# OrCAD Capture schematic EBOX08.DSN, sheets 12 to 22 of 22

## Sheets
12 13 HDMI: size A4
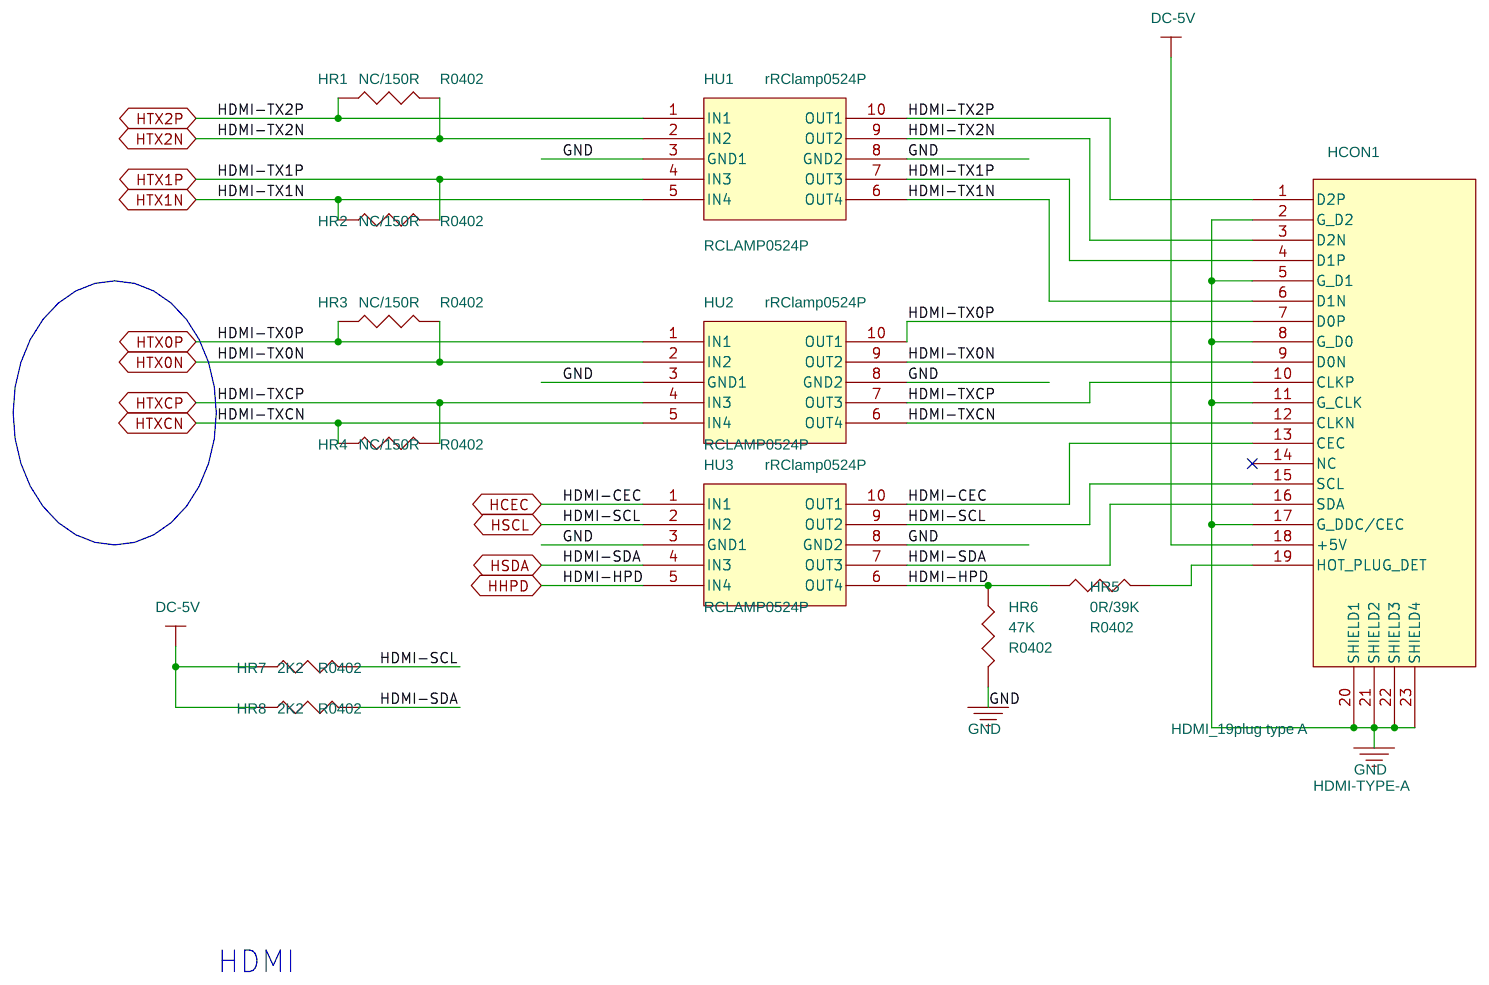
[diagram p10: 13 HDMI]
13 14 UART0-EMAC: size A2
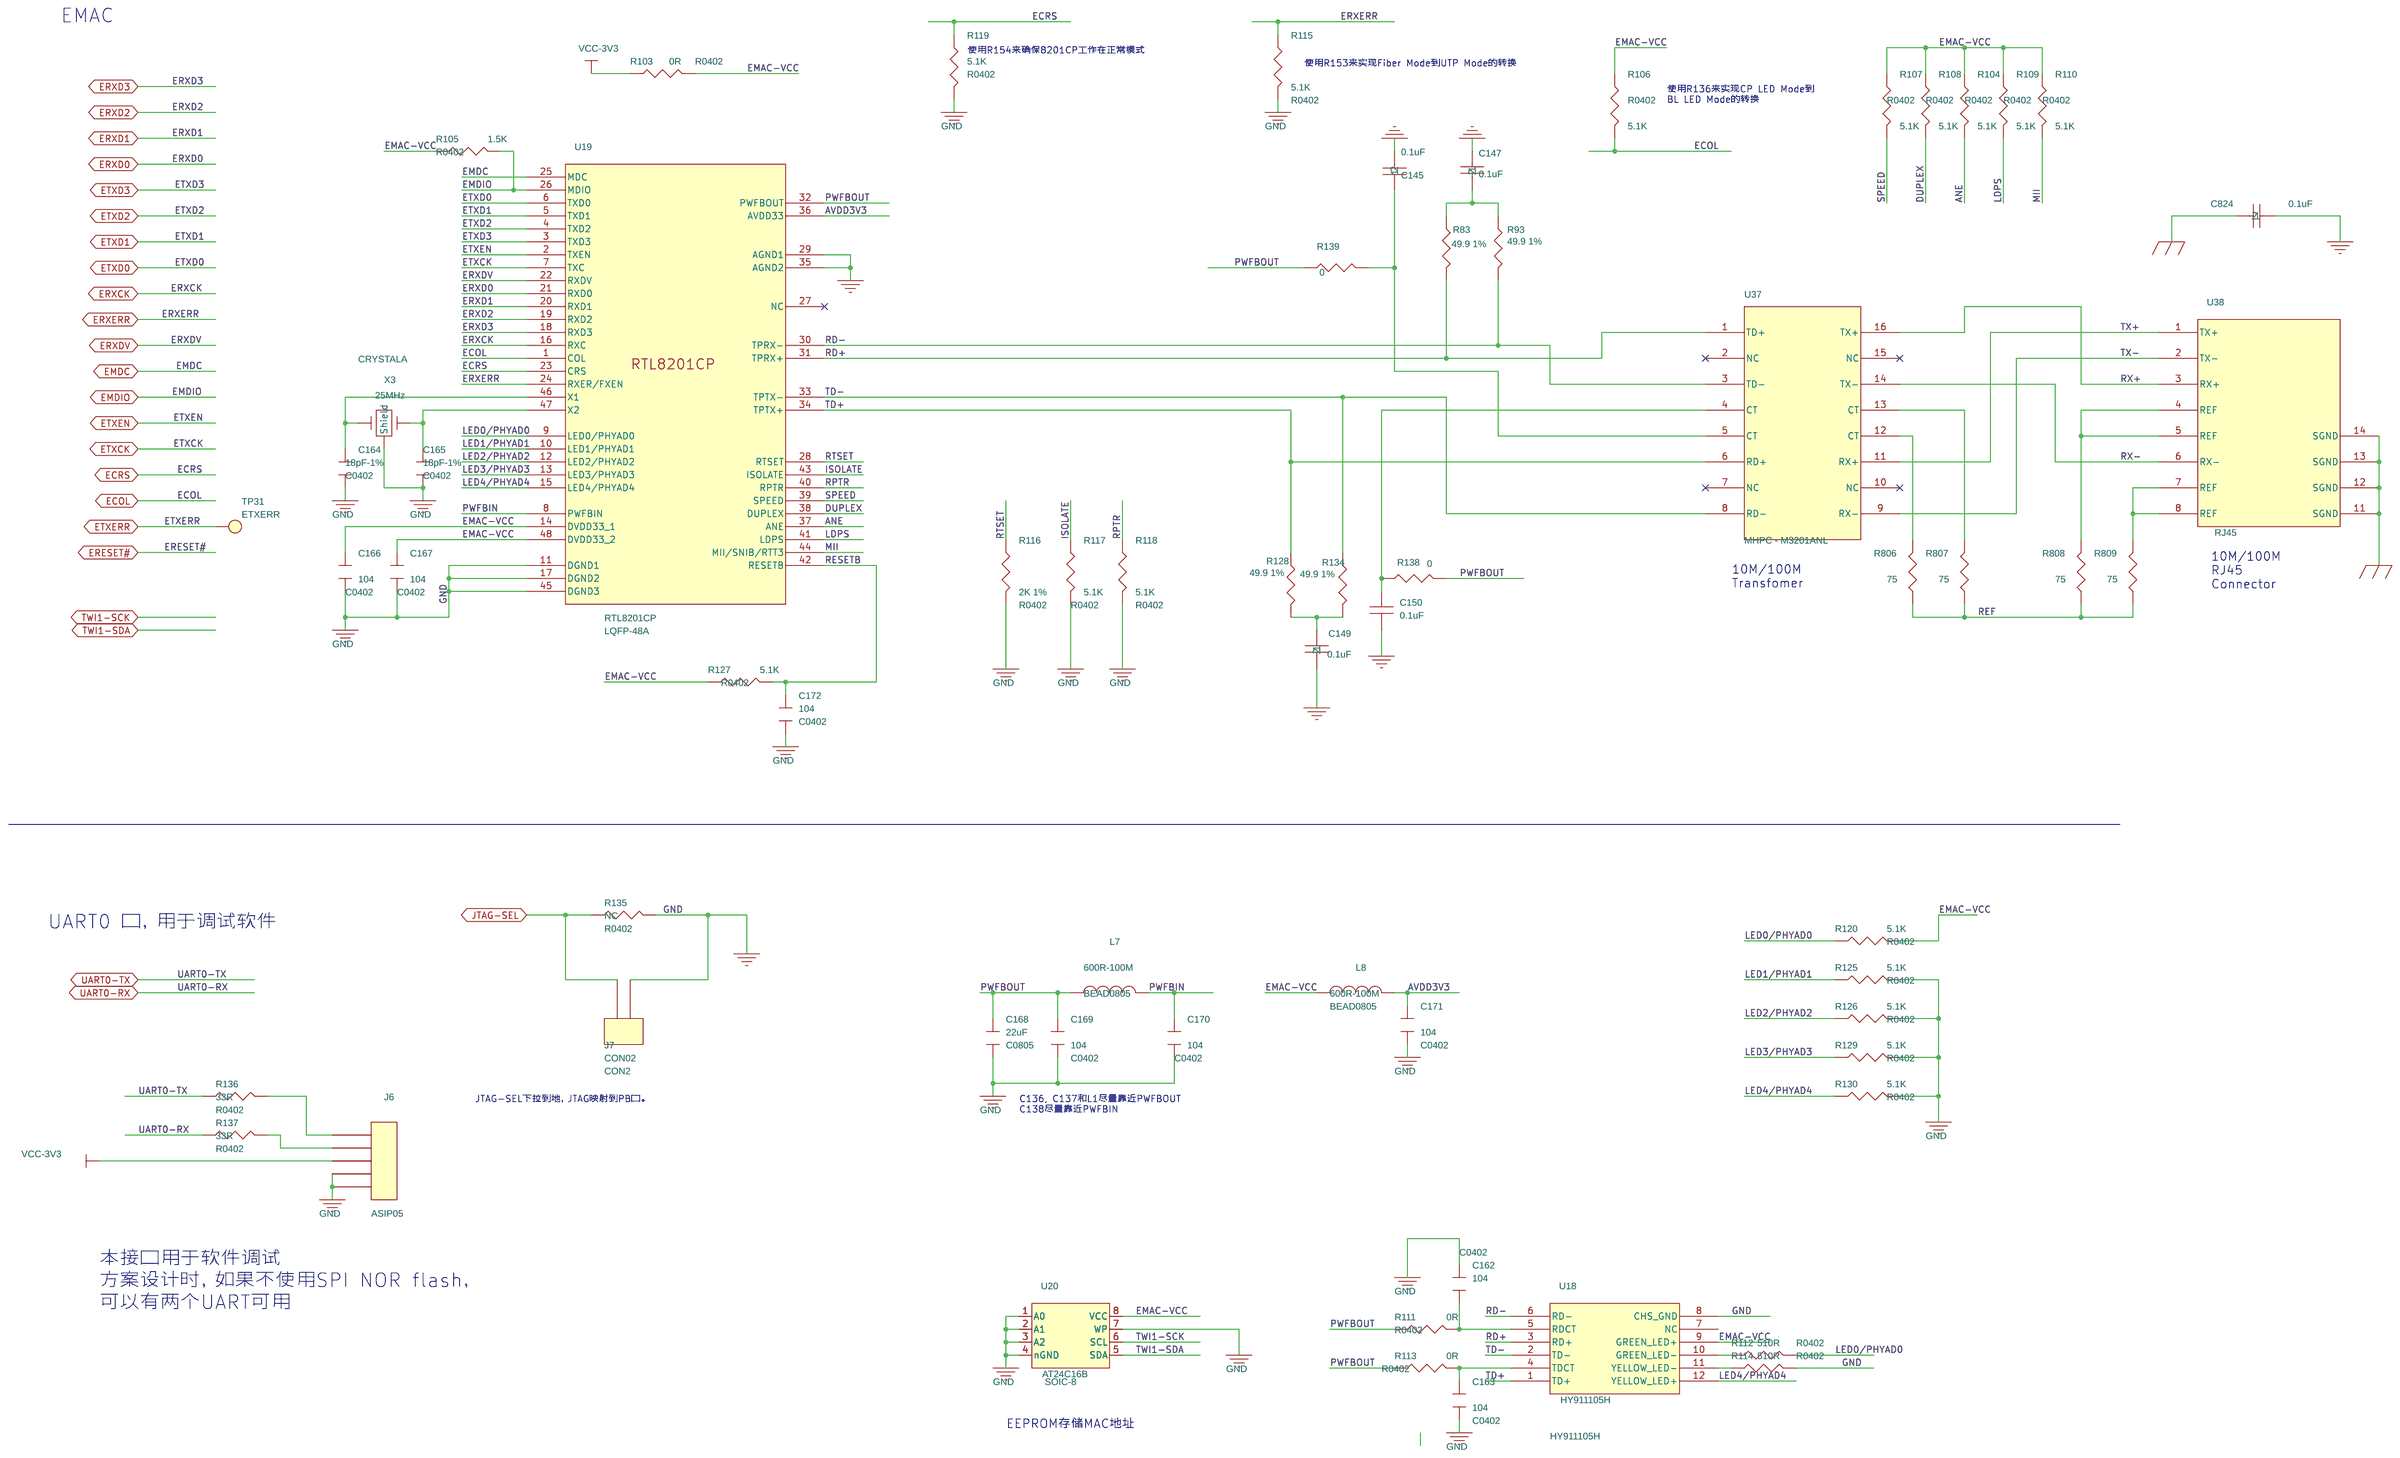
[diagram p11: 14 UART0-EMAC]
14 15 KEY-IR-LED: size A3
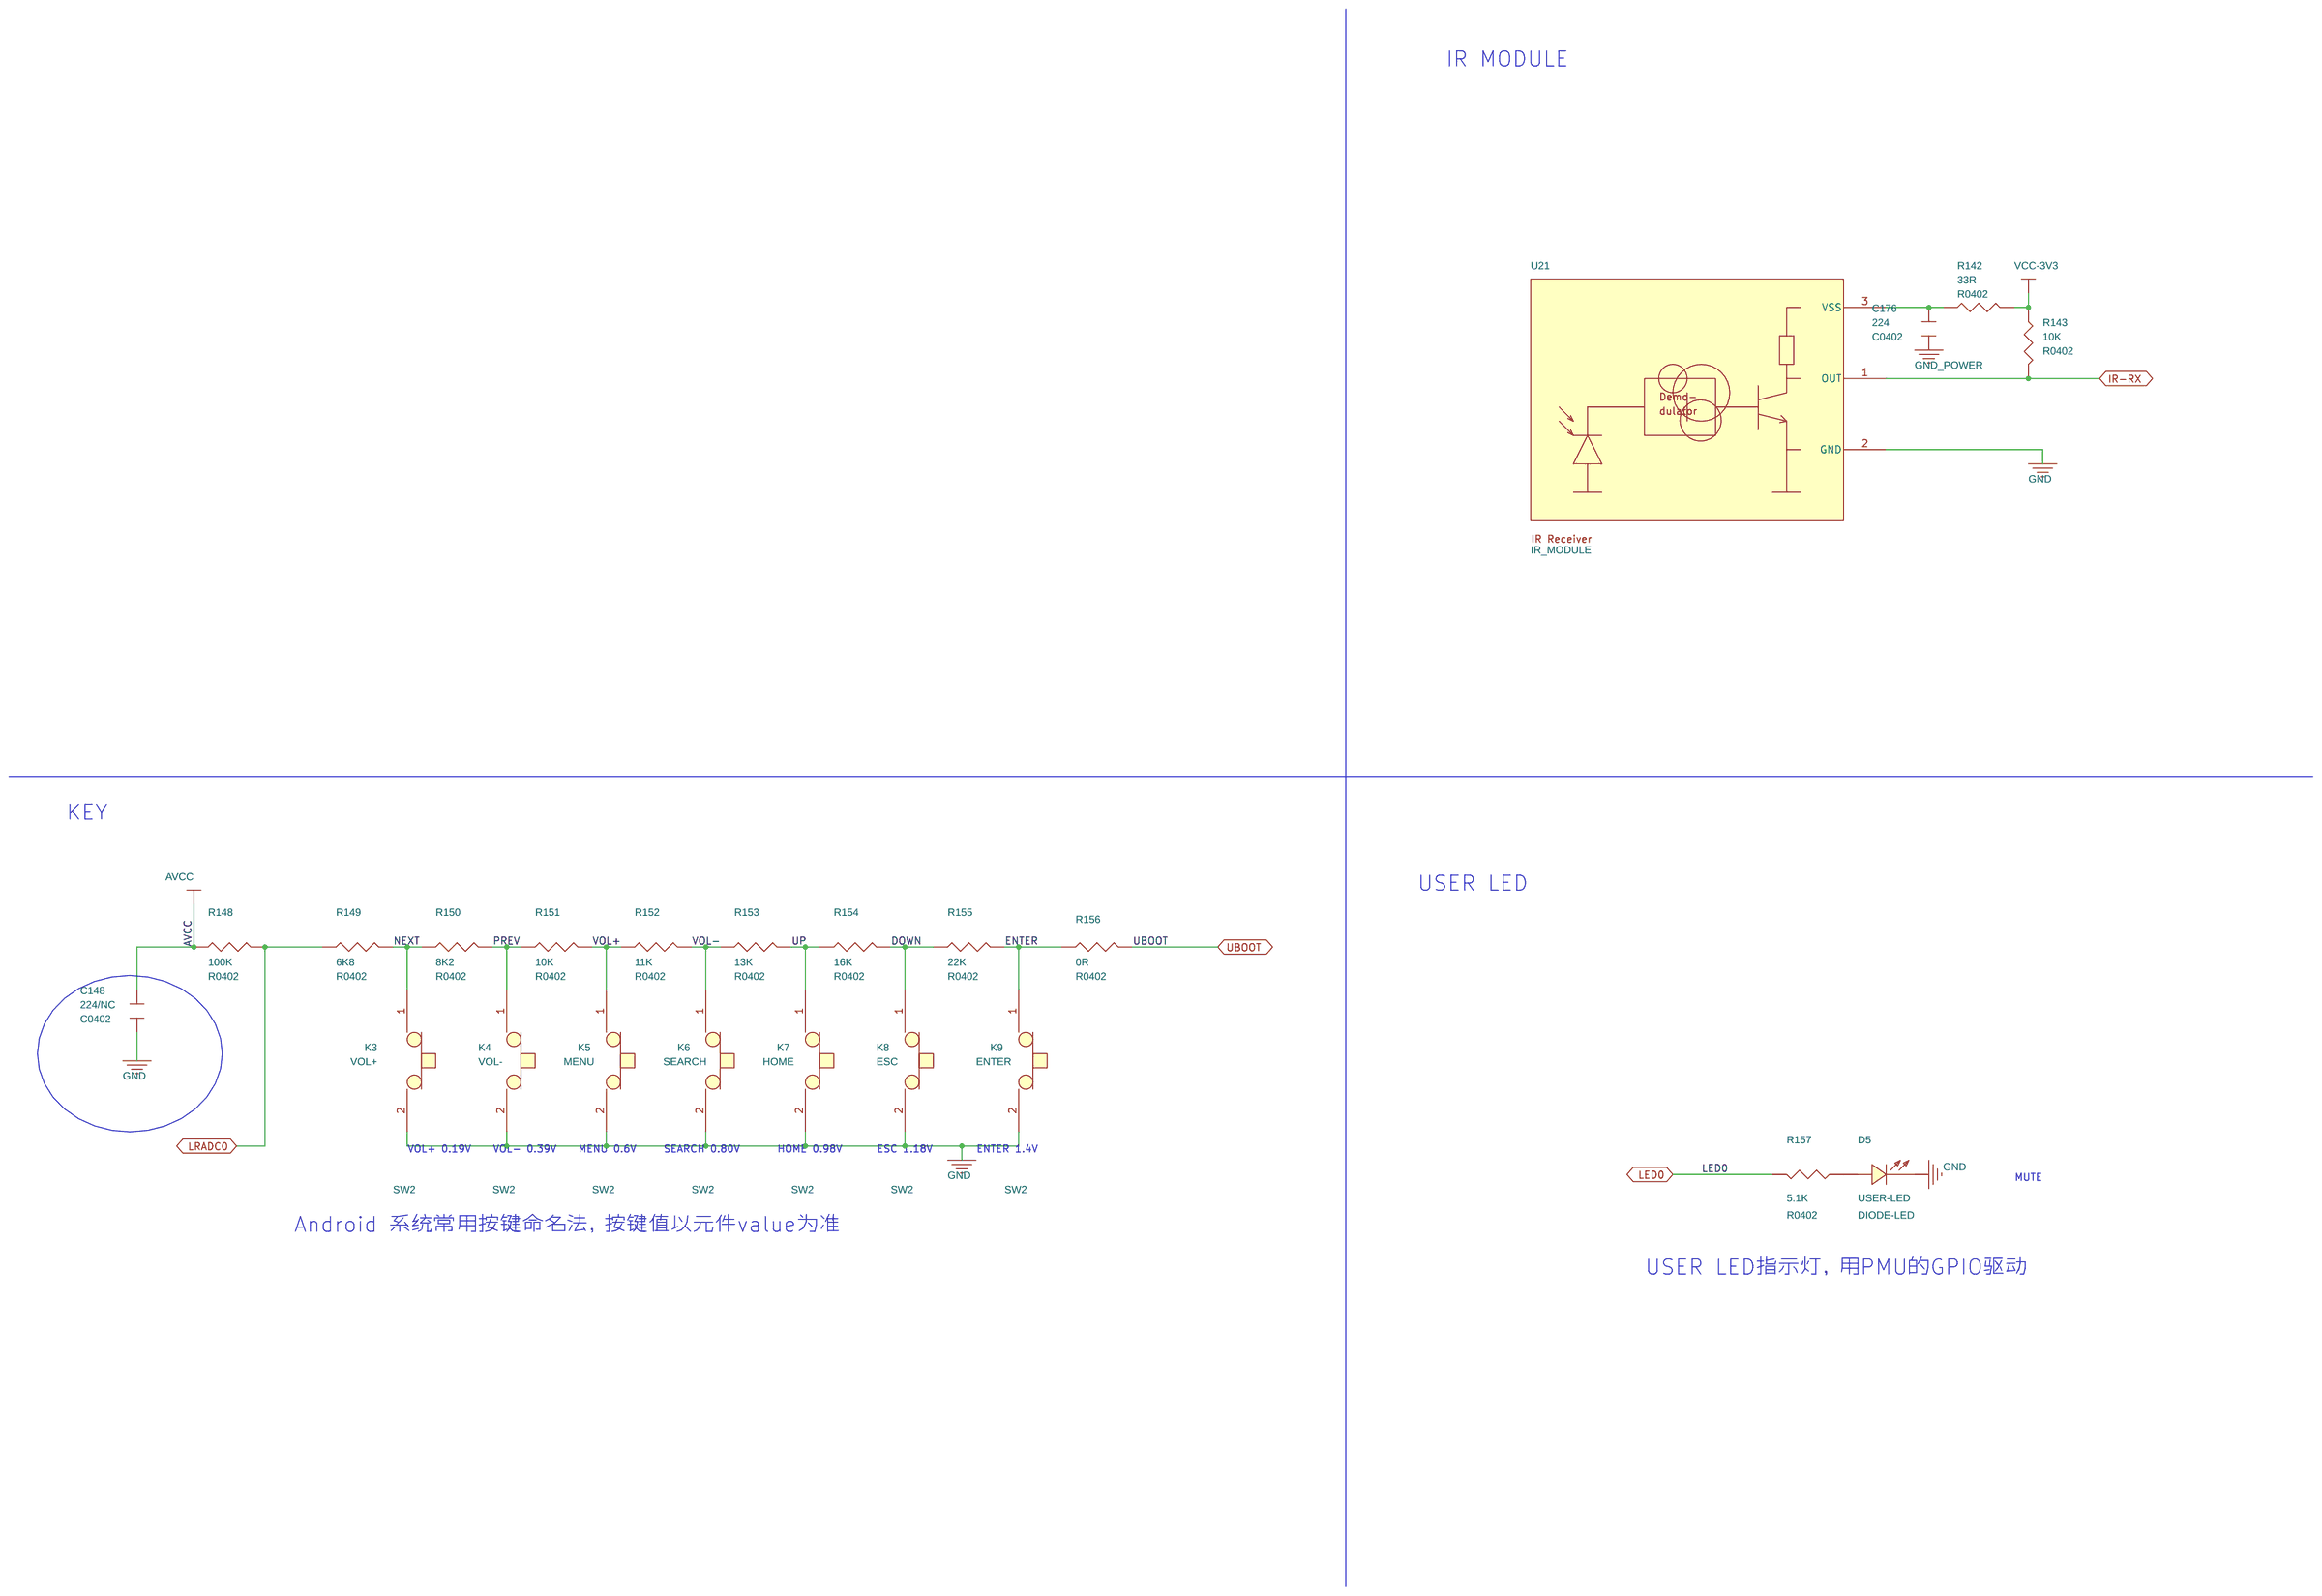
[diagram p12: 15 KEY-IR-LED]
15 16 NC
16 17 SPDIF-OUT: size A4
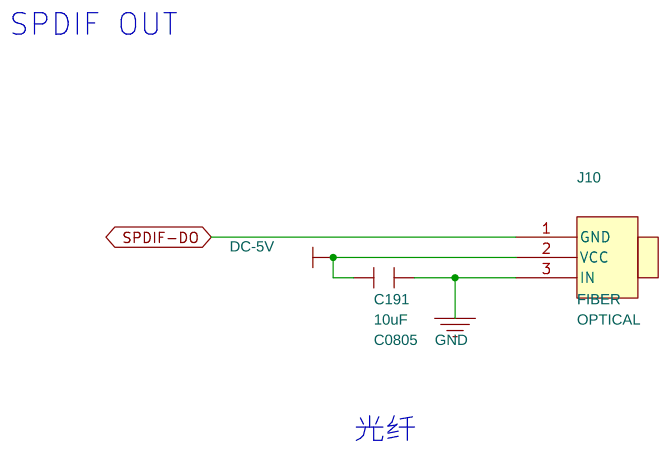
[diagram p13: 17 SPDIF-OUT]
17 18 AUDIO-OUT: size A3
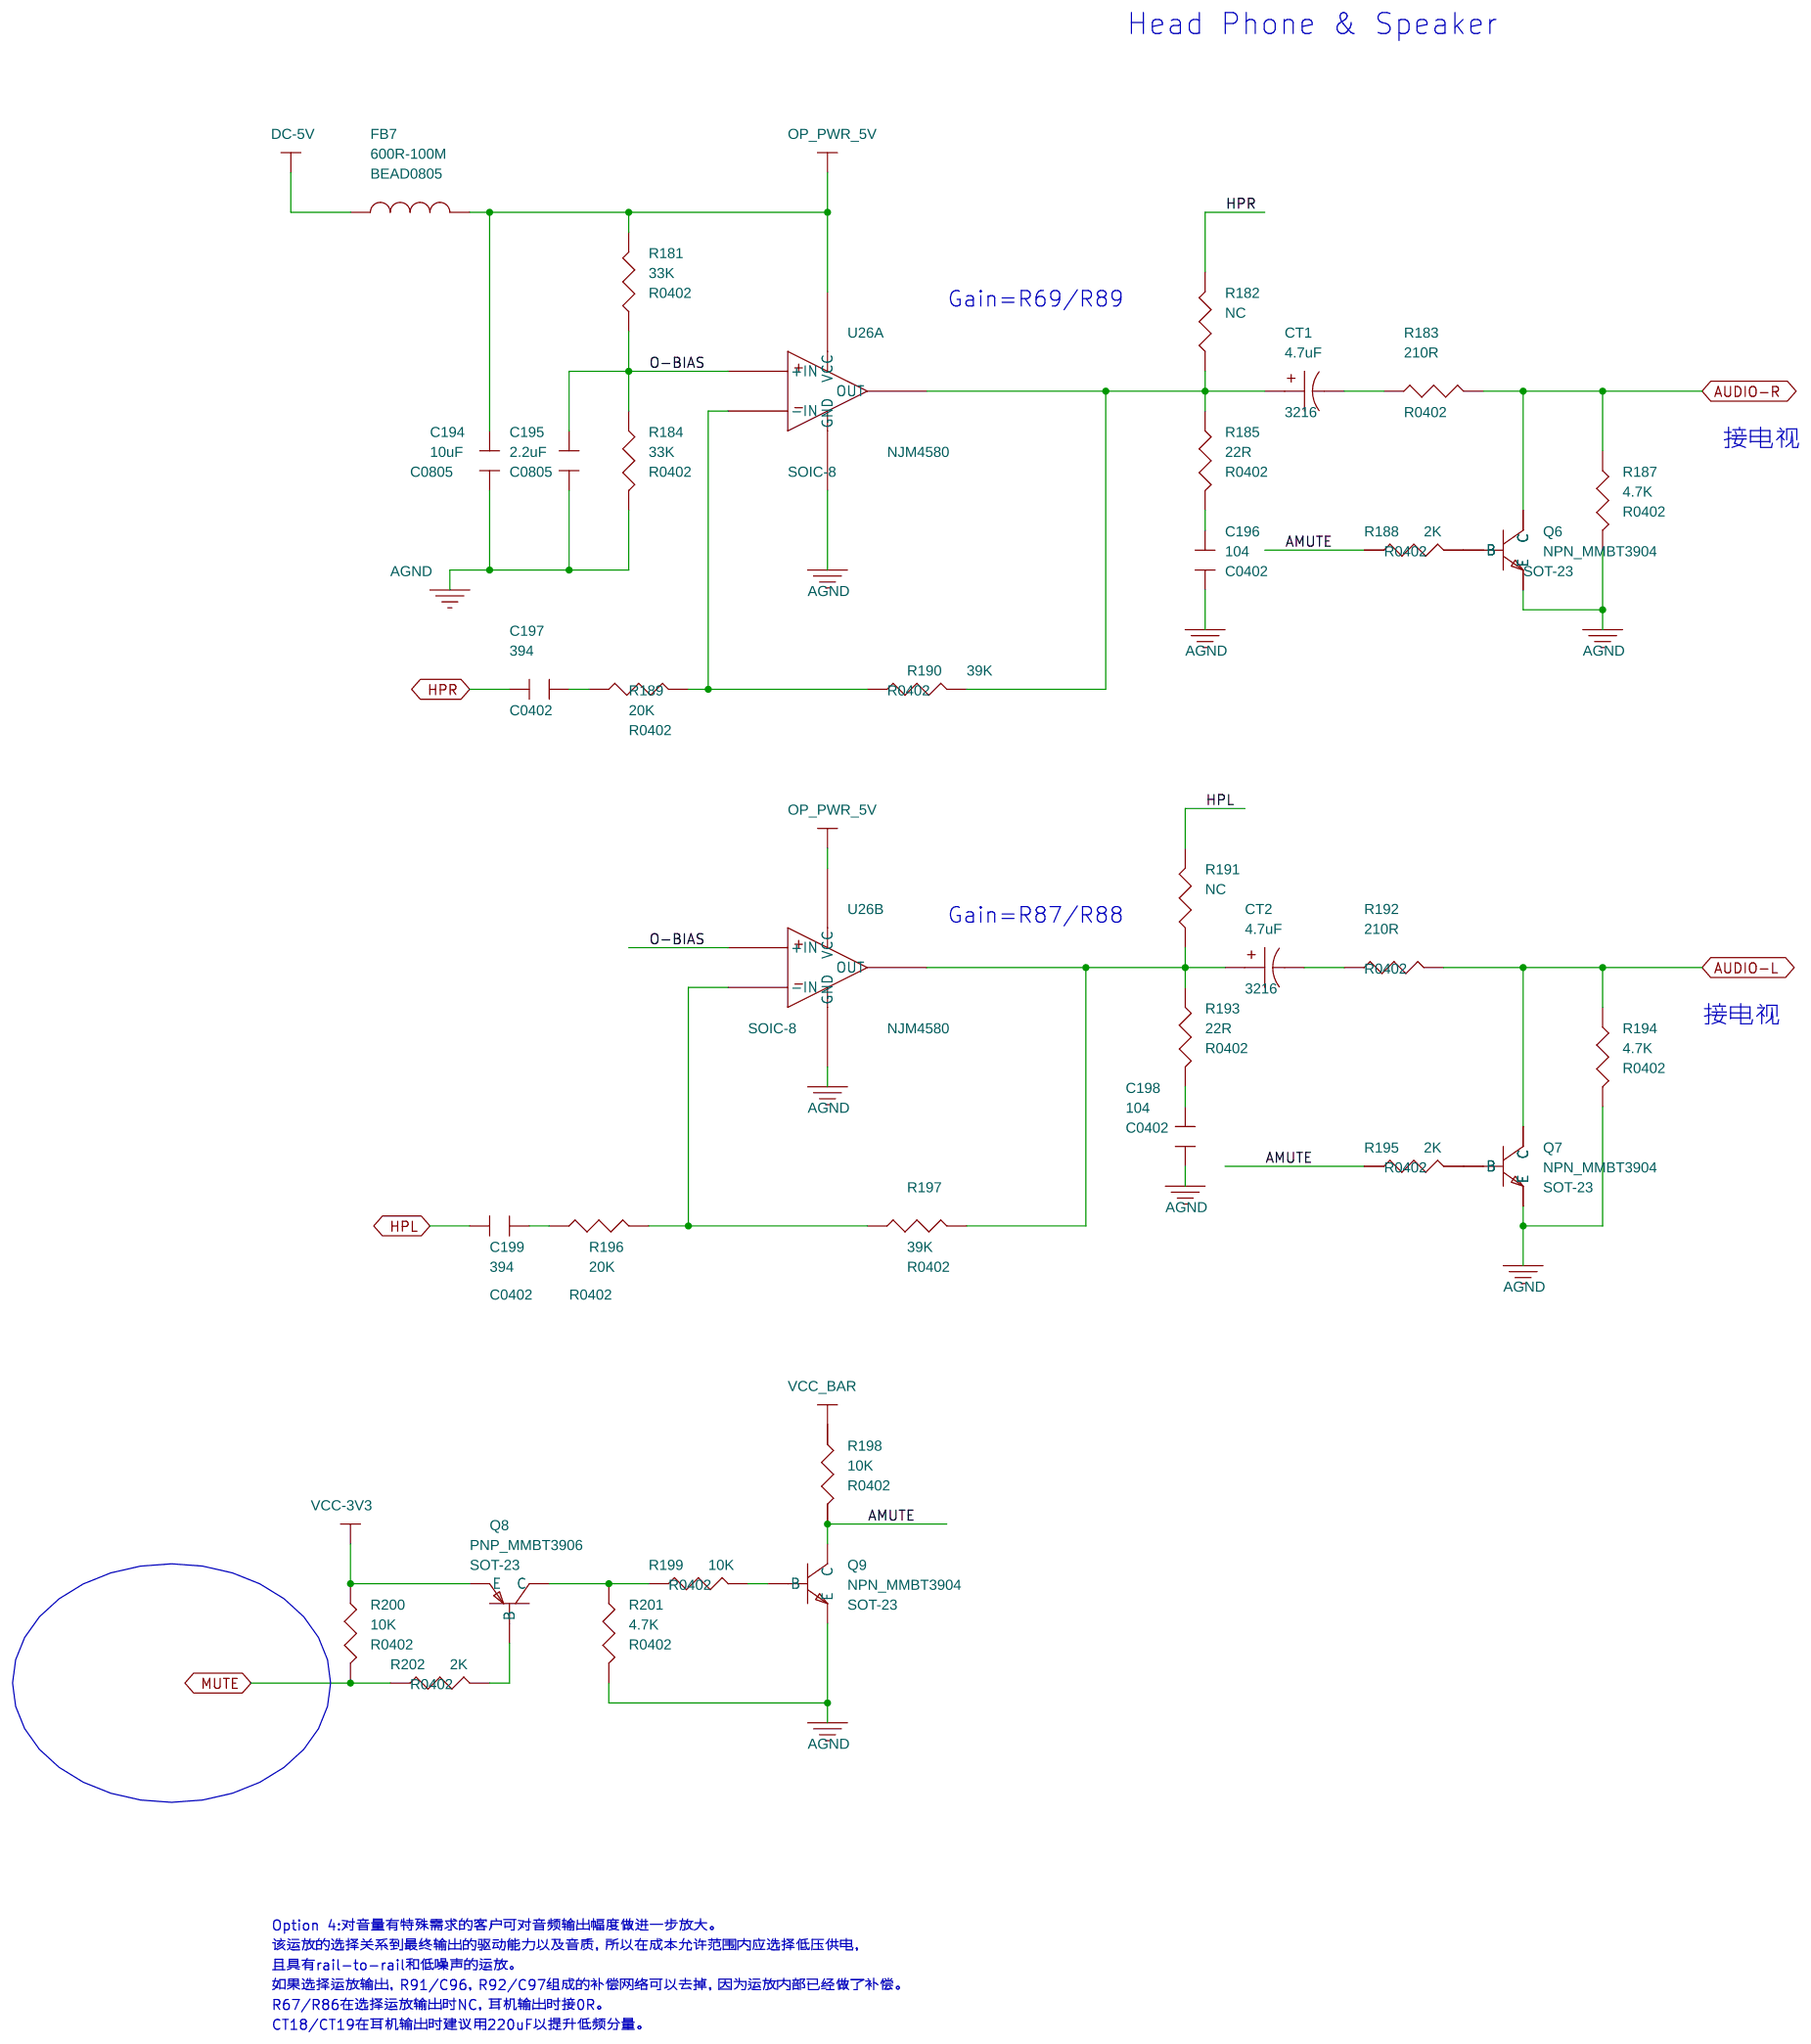
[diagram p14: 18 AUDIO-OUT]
18 19 CVBS-OUT: size A4
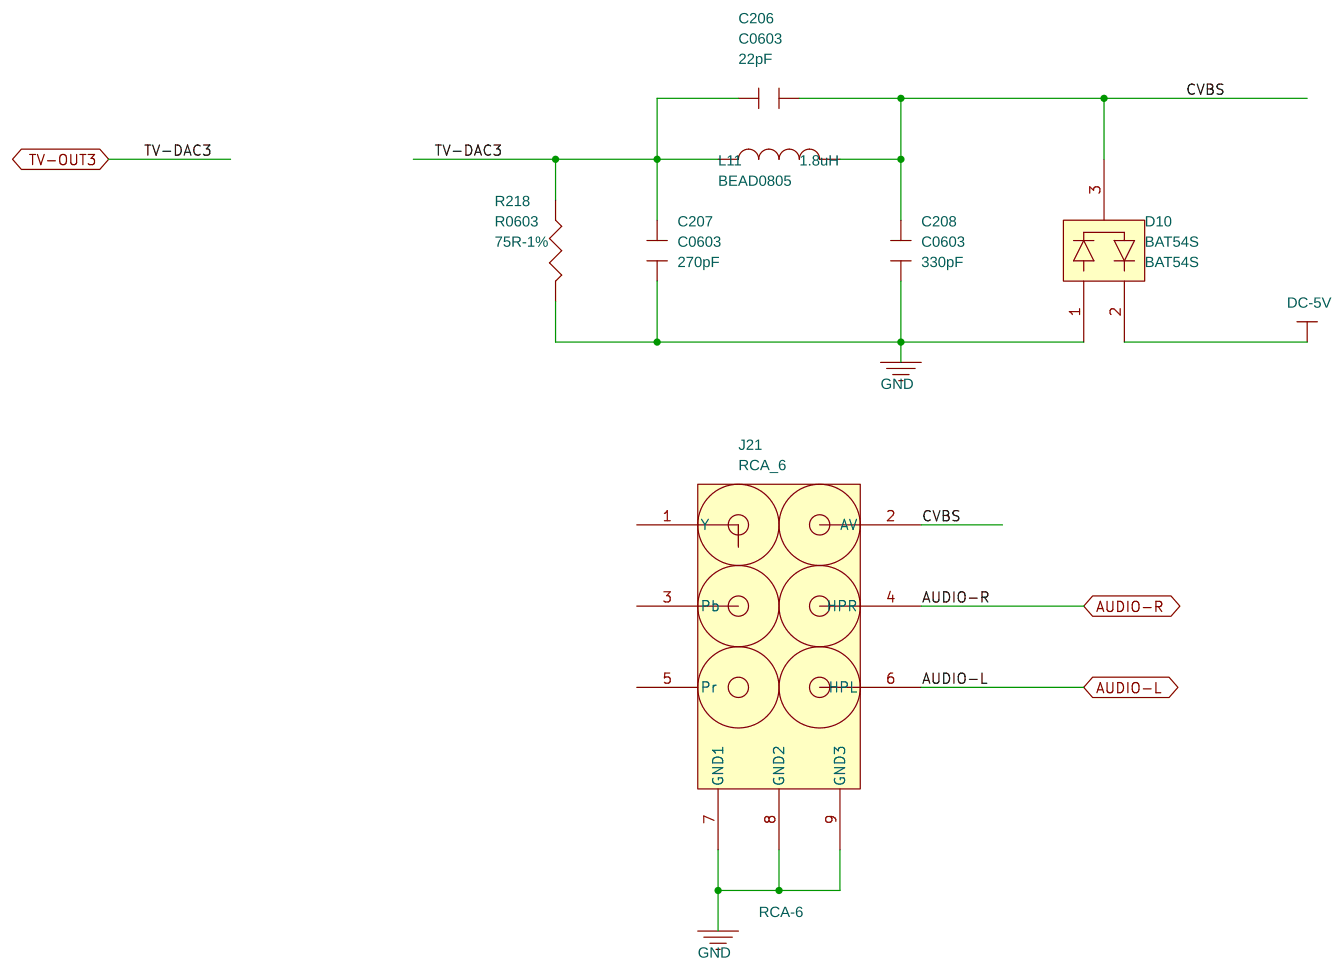
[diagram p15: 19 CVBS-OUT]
19 20 NC
20 21 NC
21 08 POWER/PMU: size A3
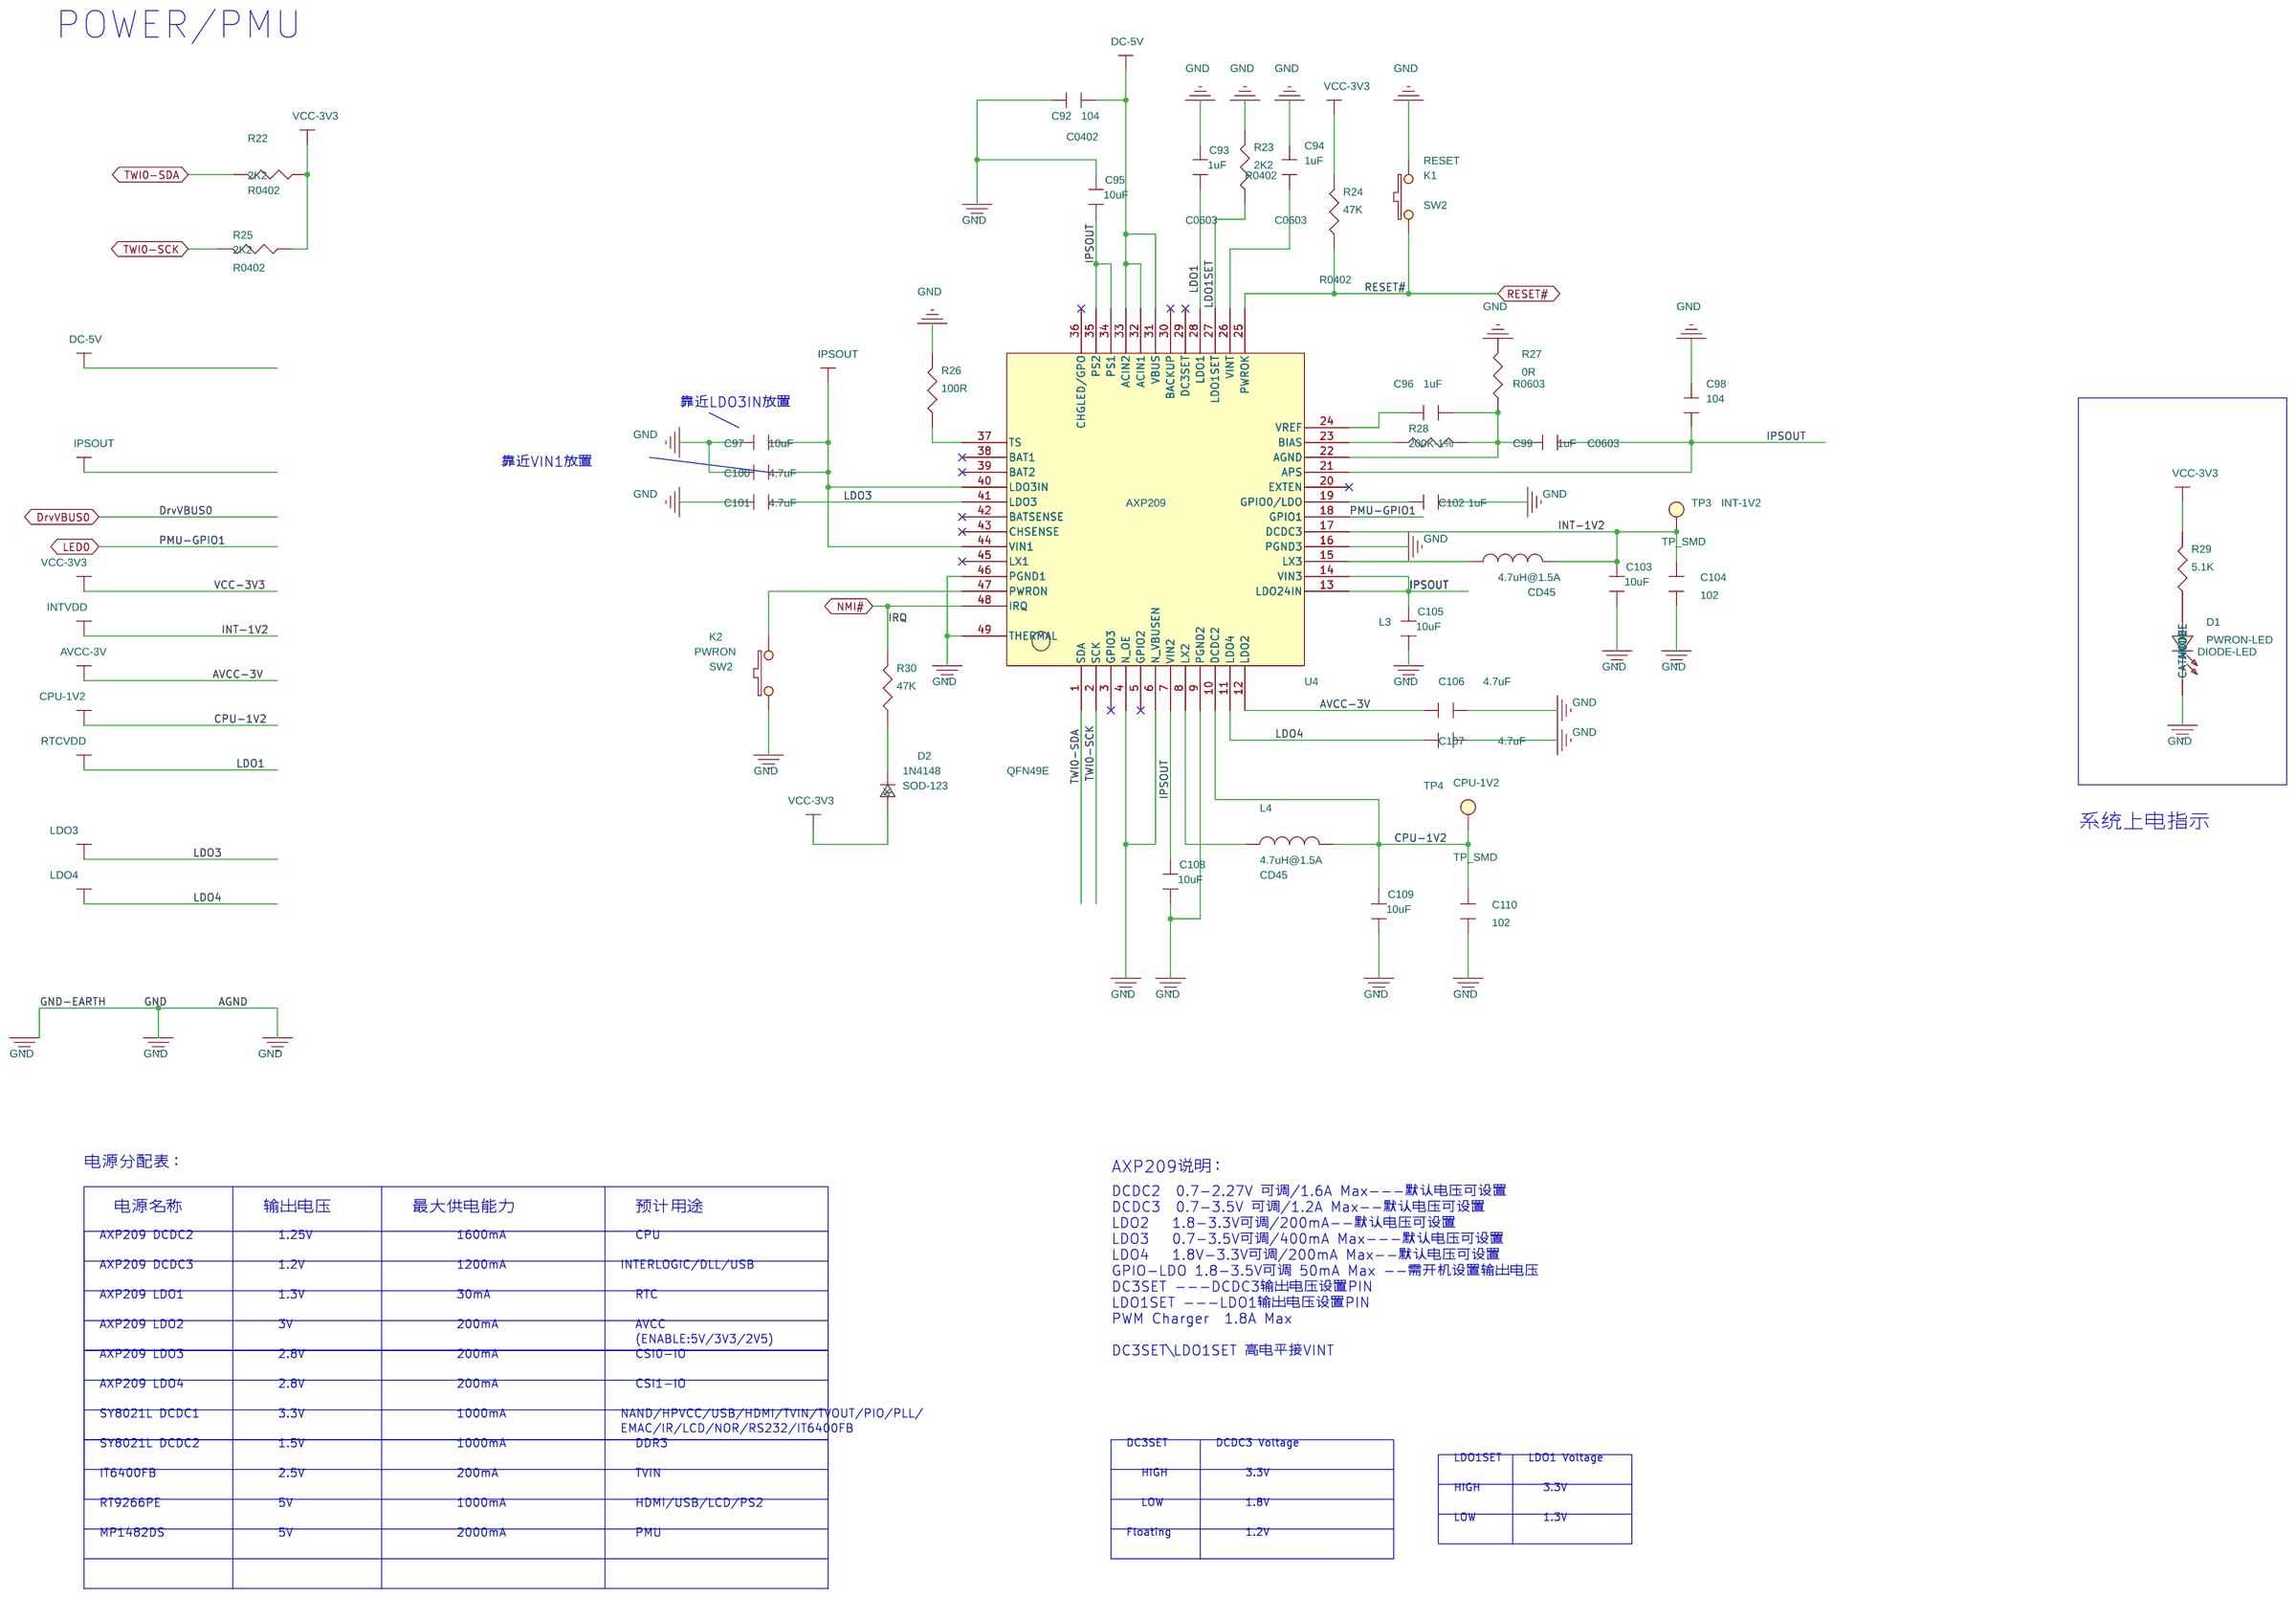
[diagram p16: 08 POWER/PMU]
22 07 POWER/DCDC: size A3
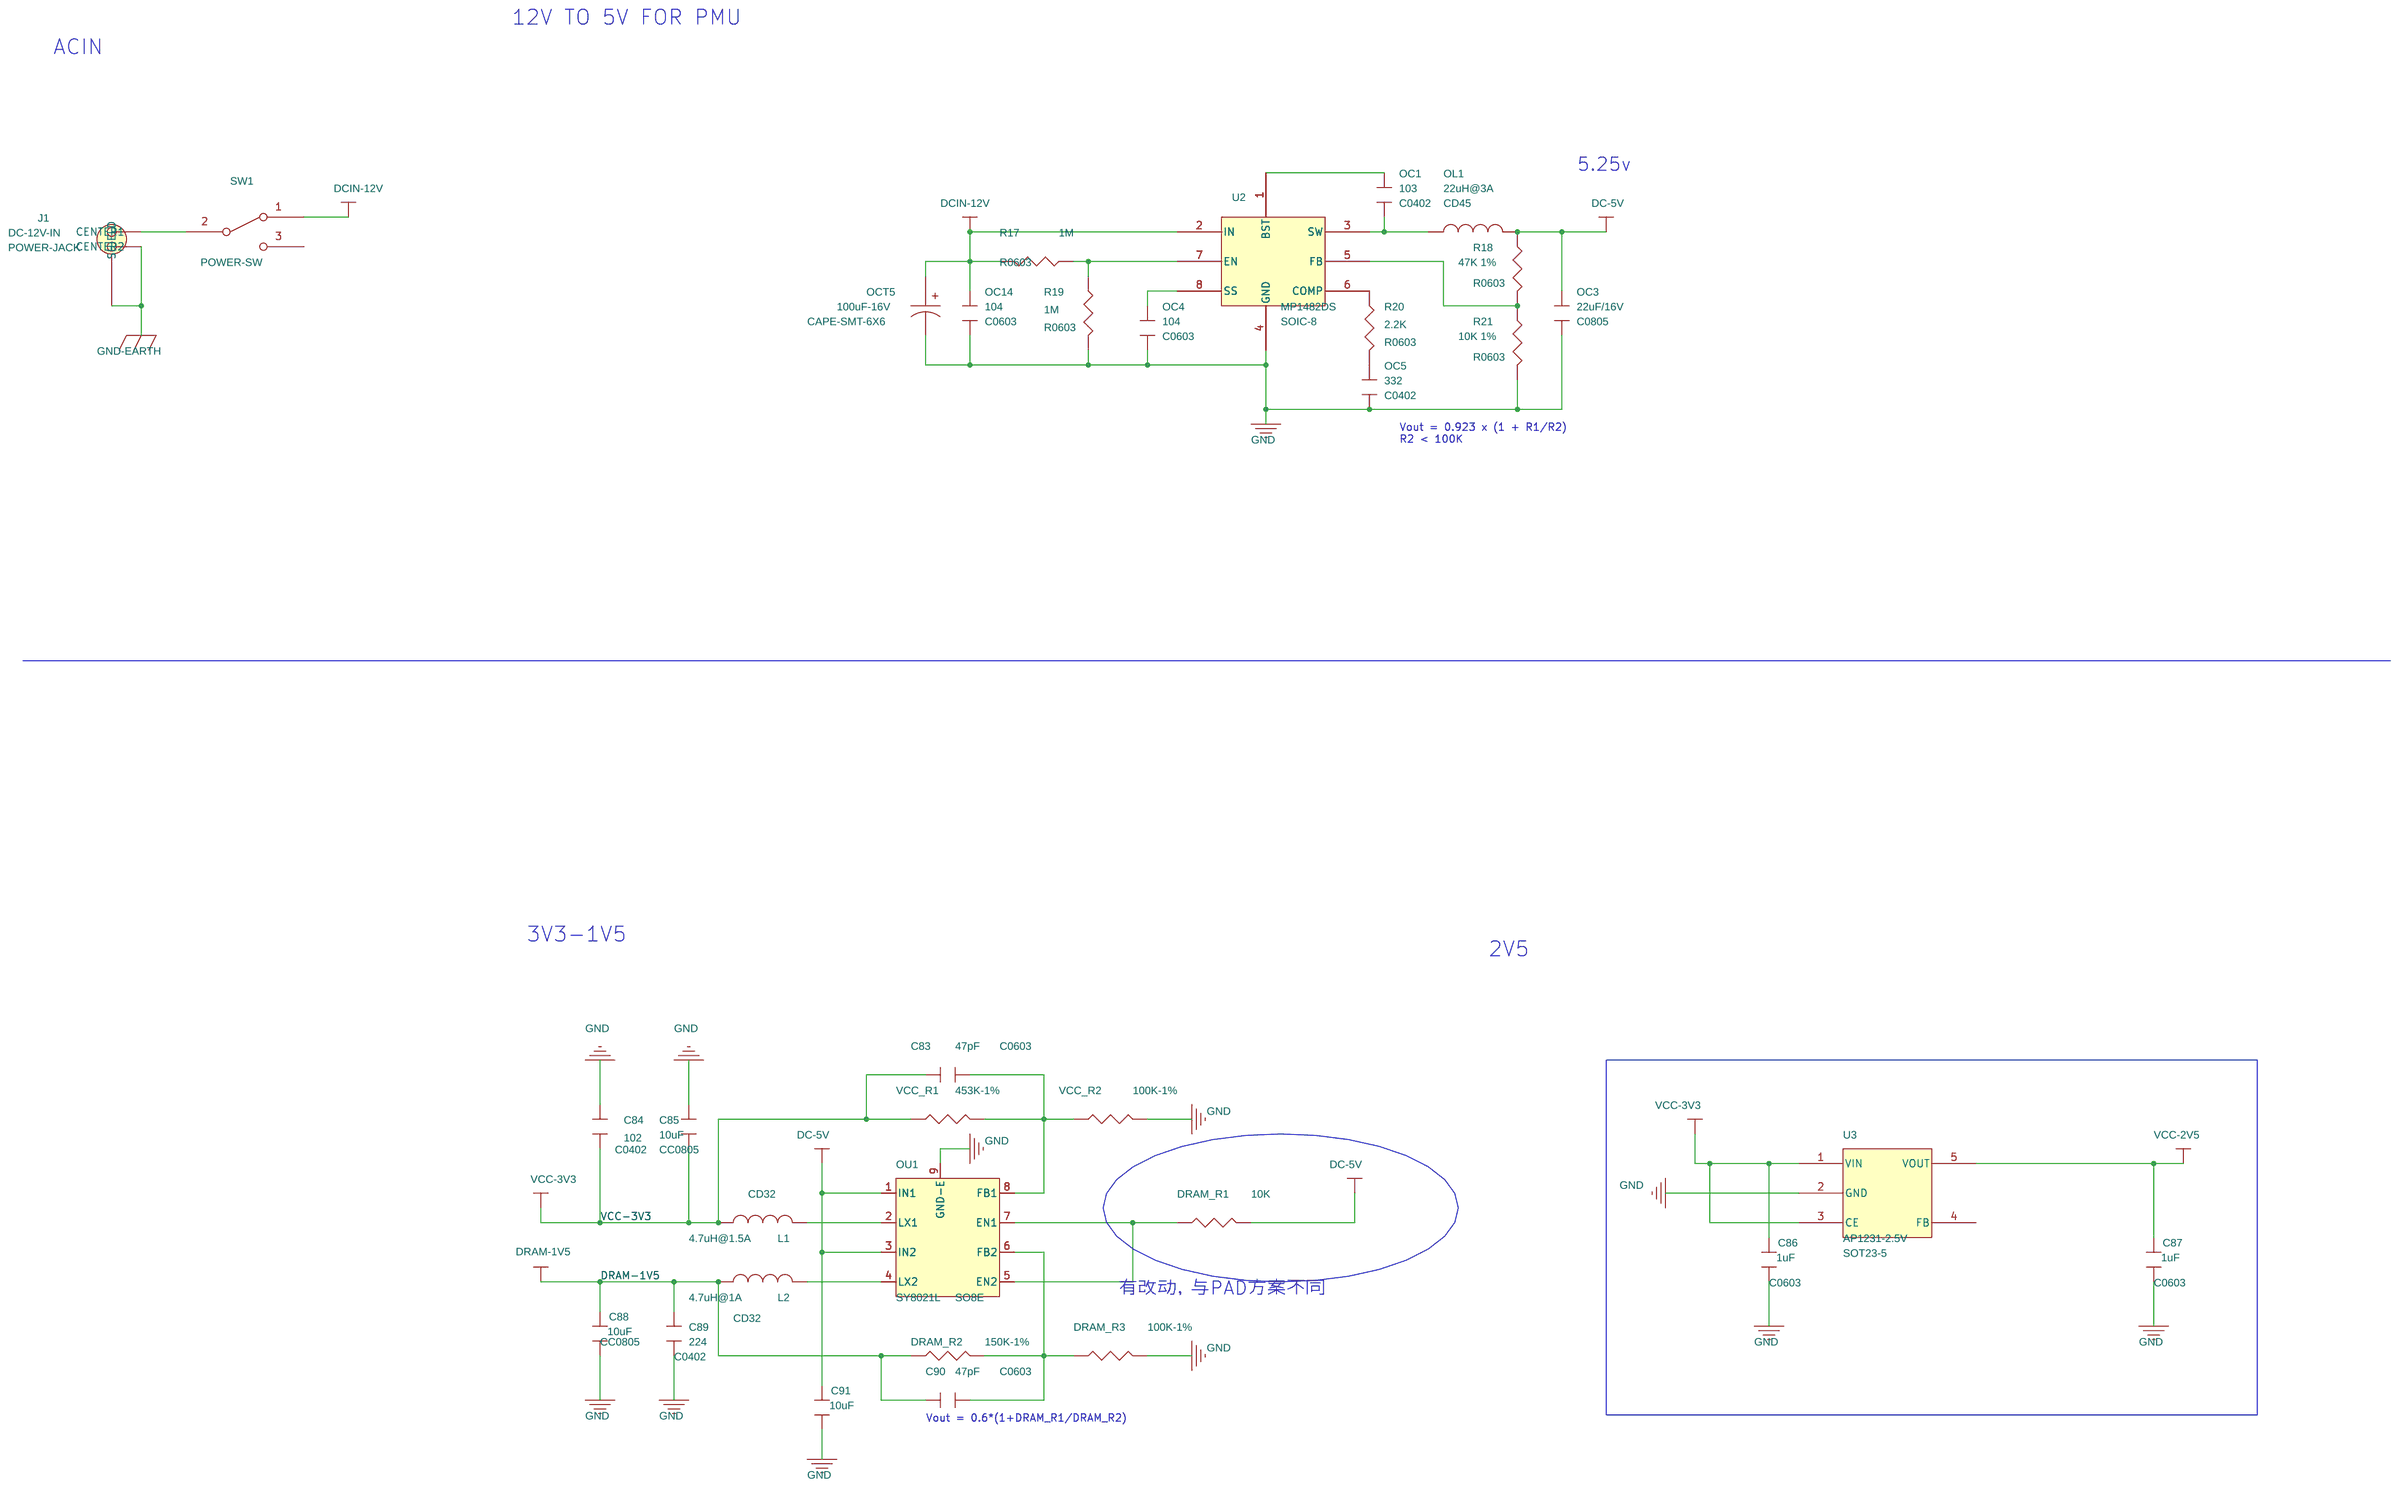
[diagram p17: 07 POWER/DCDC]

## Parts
sheet 07 POWER/DCDC
C83  47pF  [C0603]
C84  102  [C0402]
C85  10uF  [CC0805]
C86  1uF  [C0603]
C87  1uF  [C0603]
C88  10uF  [CC0805]
C89  224  [C0402]
C90  47pF  [C0603]
C91  10uF  [CC0805]
DRAM_R1  10K  [R0402]
DRAM_R2  150K-1%  [R0402]
DRAM_R3  100K-1%  [R0402]
J1  DC-12V-IN  [POWER-JACK]
L1  4.7uH@1.5A  [CD32]
L2  4.7uH@1A  [CD32]
OC1  103  [C0402]
OC3  22uF/16V  [C0805]
OC4  104  [C0603]
OC5  332  [C0402]
OC14  104  [C0603]
OCT5  100uF-16V  [CAPE-SMT-6X6]
OL1  22uH@3A  [CD45]
OU1  SY8021L  [SO8E]
R17  1M  [R0603]
R18  47K 1%  [R0603]
R19  1M  [R0603]
R20  2.2K  [R0603]
R21  10K 1%  [R0603]
SW1  POWER-SW  [SW1]
U2  MP1482DS  [SOIC-8]
U3  AP1231-2.5V  [SOT23-5]
VCC_R1  453K-1%  [R0402]
VCC_R2  100K-1%  [R0402]
sheet 08 POWER/PMU
C92  104  [C0402]
C93  1uF  [C0603]
C94  1uF  [C0603]
C95  10uF  [CC0805]
C96  1uF  [CC0603]
C97  10uF  [CC0805]
C98  104  [CC0603]
C99  1uF  [C0603]
C100  4.7uF  [CC0805]
C101  4.7uF  [CC0805]
C102  1uF  [CC0603]
C103  10uF  [CC0805]
C104  102  [C0402]
C105  10uF  [CC0805]
C106  4.7uF  [CC0805]
C107  4.7uF  [CC0805]
C108  10uF  [CC0805]
C109  10uF  [CC0805]
C110  102  [C0402]
D1  PWRON-LED  [DIODE-LED]
D2  1N4148  [SOD-123]
K1  RESET  [SW2]
K2  PWRON  [SW2]
L3  4.7uH@1.5A  [CD45]
L4  4.7uH@1.5A  [CD45]
R22  2K2  [R0402]
R23  2K2  [R0402]
R24  47K  [R0402]
R25  2K2  [R0402]
R26  100R  [R0402]
R27  0R  [R0603]
R28  200K-1%  [R0402]
R29  5.1K  [R0402]
R30  47K  [R0402]
TP3  INT-1V2  [TP_SMD]
TP4  CPU-1V2  [TP_SMD]
U4  AXP209  [QFN49E]
sheet 13 HDMI
HCON1  HDMI_19plug type A  [HDMI-TYPE-A]
HR1  NC/150R  [R0402]
HR2  NC/150R  [R0402]
HR3  NC/150R  [R0402]
HR4  NC/150R  [R0402]
HR5  0R/39K  [R0402]
HR6  47K  [R0402]
HR7  2K2  [R0402]
HR8  2K2  [R0402]
HU1  rRClamp0524P  [RCLAMP0524P]
HU2  rRClamp0524P  [RCLAMP0524P]
HU3  rRClamp0524P  [RCLAMP0524P]
sheet 14 UART0-EMAC
C145  0.1uF  [C1608]
C147  0.1uF  [C1608]
C149  0.1uF  [C1608]
C150  0.1uF  [C1608]
C162  104  [C0402]
C163  104  [C0402]
C164  18pF-1%  [C0402]
C165  18pF-1%  [C0402]
C166  104  [C0402]
C167  104  [C0402]
C168  22uF  [C0805]
C169  104  [C0402]
C170  104  [C0402]
C171  104  [C0402]
C172  104  [C0402]
C824  0.1uF  [0603C]
J6  CON05  [ASIP05]
J7  CON02  [CON2]
L7  600R-100M  [BEAD0805]
L8  600R-100M  [BEAD0805]
R83  49.9 1%  [R0603]
R93  49.9 1%  [R0603]
R103  0R  [R0402]
R104  5.1K  [R0402]
R105  1.5K  [R0402]
R106  5.1K  [R0402]
R107  5.1K  [R0402]
R108  5.1K  [R0402]
R109  5.1K  [R0402]
R110  5.1K  [R0402]
R111  0R  [R0402]
R112  510R  [R0402]
R113  0R  [R0402]
R114  510R  [R0402]
R115  5.1K  [R0402]
R116  2K 1%  [R0402]
R117  5.1K  [R0402]
R118  5.1K  [R0402]
R119  5.1K  [R0402]
R120  5.1K  [R0402]
R125  5.1K  [R0402]
R126  5.1K  [R0402]
R127  5.1K  [R0402]
R128  49.9 1%  [R0603]
R129  5.1K  [R0402]
R130  5.1K  [R0402]
R134  49.9 1%  [R0603]
R135  NC  [R0402]
R136  33R  [R0402]
R137  33R  [R0402]
R138  0  [R0603]
R139  0  [R0603]
R806  75  [0603R]
R807  75  [0603R]
R808  75  [0603R]
R809  75  [0603R]
TP31  ETXERR  [TP_SMD]
U18  HY911105H  [HY911105H]
U19  RTL8201CP  [LQFP-48A]
U20  AT24C16B  [SOIC-8]
U37  MHPC - M3201ANL  [XSFORMER]
U38  RJ45  [RJ45]
X3  25MHz  [CRYSTALA]
sheet 15 KEY-IR-LED
C148  224/NC  [C0402]
C176  224  [C0402]
D5  USER-LED  [DIODE-LED]
K3  VOL+  [SW2]
K4  VOL-  [SW2]
K5  MENU  [SW2]
K6  SEARCH  [SW2]
K7  HOME  [SW2]
K8  ESC  [SW2]
K9  ENTER  [SW2]
R142  33R  [R0402]
R143  10K  [R0402]
R148  100K  [R0402]
R149  6K8  [R0402]
R150  8K2  [R0402]
R151  10K  [R0402]
R152  11K  [R0402]
R153  13K  [R0402]
R154  16K  [R0402]
R155  22K  [R0402]
R156  0R  [R0402]
R157  5.1K  [R0402]
U21  IR_MODULE  [IR_MODULE]
sheet 17 SPDIF-OUT
C191  10uF  [C0805]
J10  FIBER  [OPTICAL]
sheet 18 AUDIO-OUT
C194  10uF  [C0805]
C195  2.2uF  [C0805]
C196  104  [C0402]
C197  394  [C0402]
C198  104  [C0402]
C199  394  [C0402]
CT1  4.7uF  [3216]
CT2  4.7uF  [3216]
FB7  600R-100M  [BEAD0805]
Q6  NPN_MMBT3904  [SOT-23]
Q7  NPN_MMBT3904  [SOT-23]
Q8  PNP_MMBT3906  [SOT-23]
Q9  NPN_MMBT3904  [SOT-23]
R181  33K  [R0402]
R182  NC  [R0603]
R183  210R  [R0402]
R184  33K  [R0402]
R185  22R  [R0402]
R187  4.7K  [R0402]
R188  2K  [R0402]
R189  20K  [R0402]
R190  39K  [R0402]
R191  NC  [R0603]
R192  210R  [R0402]
R193  22R  [R0402]
R194  4.7K  [R0402]
R195  2K  [R0402]
R196  20K  [R0402]
R197  39K  [R0402]
R198  10K  [R0402]
R199  10K  [R0402]
R200  10K  [R0402]
R201  4.7K  [R0402]
R202  2K  [R0402]
U26  NJM4580  [SOIC-8]  (sections A,B)
sheet 19 CVBS-OUT
C206  22pF  [C0603]
C207  270pF  [C0603]
C208  330pF  [C0603]
D10  BAT54S  [BAT54S]
J21  RCA_6  [RCA-6]
L11  1.8uH  [BEAD0805]
R218  75R-1%  [R0603]

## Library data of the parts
C83 C84 C89 C90 C104 C110 = CAPACITOR_1: PAGE: 1
C85-C88 C91-C103 C105-C109 = CAPACITOR_0: PAGE: 1
DRAM_R1-DRAM_R3 R17-R30 R83 R93 R135-R137 R142 R143 R157 VCC_R1 VCC_R2 = R
J1 = BNC-2
FB7 L1-L4 L11 OL1 = INDUCTOR
C191 C194-C199 C206-C208 OC1 OC3-OC5 OC14 = CAPACITOR_v2
CT1 CT2 OCT5 = CAPACITOR_POL
OU1 = RT9266PE_1
SW1 = SW_SPDT
U2 = PM1066
U3 = RT9293B_0
D1 = LED_0: PAGE: 1
D2 = 1N4500
K1 K2 = SW_TACT_SPST_SM
TP3 TP4 TP31 = T_POINT_R
U4 = AW1612_2
HCON1 = HDMI19_PLUG
HR1-HR8 R138 R139 R181-R185 R187-R202 = RESISTOR
HU1-HU3 = rRClamp0524P
C145 = CAP_NP
C147 = CAP_NP_3
C149 = CAP_NP_2
C150 = CAP
C162-C172 = CAP_v2
C824 = CAP_NP_1: CHIP 0.1uF 50V X7R; PART ID: 65K0603104 32
J6 = CON2_2
J7 = CON2
L7 L8 = INDUCTOR_0805
R103-R120 R125-R127 R129 R130 R148-R156 = R1_0805
R128 R134 = R_0
R806-R809 = R: CHIP 75 OHM 1/16W; A/I?: SMT; PART ID: 61P0603332
U18 = HY911105H
U19 = Realtek_RTL8201CP_0
U20 = AT24C16B
U37 = TS6121U: NIC, Transformer,TS6121CX
U38 = RJ45_0: RJ-45 Connecter For 10/100M
X3 = CRYSTAL_XCOL-3
C148 C176 = CAPACITOR_0: PAGE: 2
D5 = LED
K3-K9 = KEY-2PIN_0
U21 = IR_Module
J10 = FIBER
Q6 Q7 Q9 = NPN_MMBT3904
Q8 = PNP_0
U26 = NJM4580_SO_0
D10 = DIODE_DUAL
J21 = RCA_6
R218 = RESISTOR: ROOM: TVLCD

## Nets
AGND: C84.2 C85.2 C86.2 C87.2 C88.2 C89.2 C91.2 C92.2 C93.1 C94.2 C95.1 C97.1 C98.2 C100.1 C101.1 C102.2 C103.2 C104.2 C105.2 C106.2 C107.2 C108.2 C109.2 C110.2 C145.2 C147.1 C148.1 C149.2 C150.2 C162.2 C163.1 C164.1 C165.1 C166.1 C167.1 C168.1 C169.1 C170.1 C171.1 C172.1 C176.1 C191.2 C194.1 C195.1 C196.1 C198.1 C207.1 C208.1 C824.1 D1.2(CATHODE) D5.2(CATHODE) D10.1 DRAM_R3.2 HCON1.2(G_D2) HCON1.5(G_D1) HCON1.8(G_D0) HCON1.11(G_CLK) HCON1.17(G_DDC/CEC) HCON1.20(SHIELD1) HCON1.21(SHIELD2) HCON1.22(SHIELD3) HCON1.23(SHIELD4) HR6.2 HU1.3(GND1) HU1.8(GND2) HU2.3(GND1) HU2.8(GND2) HU3.3(GND1) HU3.8(GND2) J1.2(CENTER2) J1.3(SHIELD) J6.1 J6.2 J7.2 J10.3(IN) J21.7(GND1) J21.8(GND2) J21.9(GND3) K1.2 K2.1 K3.2 K4.2 K5.2 K6.2 K7.2 K8.2 K9.2 OC3.1 OC4.1 OC5.1 OC14.1 OCT5.2 OU1.9(GND-E) Q6.2(E) Q7.2(E) Q9.2(E) R19.2 R21.2 R23.2 R26.2 R27.2 R114.2 R115.2 R116.2 R117.2 R118.2 R119.2 R125.2 R126.2 R129.2 R130.2 R135.2 R184.2 R187.2 R194.2 R201.2 R218.2 U2.4(GND) U3.2(GND) U4.4(N_OE) U4.6(N_VBUSEN) U4.9(PGND2) U4.16(PGND3) U4.46(PGND1) U4.49(THERMAL) U18.8(CHS_GND) U19.11(DGND1) U19.17(DGND2) U19.29(AGND1) U19.35(AGND2) U19.45(DGND3) U20.1(A0) U20.2(A1) U20.3(A2) U20.4(nGND) U20.7(WP) U21.2(GND) U26.4(GND) VCC_R2.2 X3.3(Shield) ; also on sheet 1 5 6 7 8 9 10
AVCC: C106.1 C148.2 R148.1 U4.12(LDO2) ; also on sheet 6
AVDD3V3: C171.2 L8.2 U19.36(AVDD33)
GND_EARTH: C824.2 U38.11(SGND) U38.12(SGND) U38.13(SGND) U38.14(SGND)
VCC-2V5: C87.1 U3.5(VOUT) ; also on sheet 7
AMUTE: Q9.3(C) R188.1 R195.1 R198.2
ANE: R104.2 U19.37(ANE)
AUDIO-L: J21.6(HPL) Q7.3(C) R192.2 R194.1
AUDIO-R: J21.4(HPR) Q6.3(C) R183.2 R187.1
CPUVDD: C109.1 C110.1 L4.2 TP4.1(TP) U4.10(DCDC2) ; also on sheet 5 7
CSI0-IO-2V8: C101.2 U4.41(LDO3) ; also on sheet 5 7
CSI1-IO-2V8: C107.1 U4.11(LDO4) ; also on sheet 5 7
CVBS: C206.2 C208.2 D10.3 J21.2(AV) L11.2
DC-5V: C91.1 C92.1 C191.1 D10.2 DRAM_R1.2 FB7.1 HCON1.18(+5V) HR7.1 HR8.1 J10.2(VCC) OC3.2 OL1.2 OU1.1(IN1) OU1.3(IN2) R18.1 U4.31(VBUS) U4.32(ACIN1) U4.33(ACIN2) ; also on sheet 10
DCIN-12V: OC14.2 OCT5.1 R17.2 SW1.1(NC) U2.2(IN)
DOWN: K8.1 R154.2 R155.1
DRAM-VCC: C88.1 C89.1 C90.1 DRAM_R2.1 L2.1 ; also on sheet 5 7 8
DUPLEX: R108.2 U19.38(DUPLEX)
ECOL: R106.2 U19.1(COL) ; also on sheet 1 6
ECRS: R119.1 U19.23(CRS) ; also on sheet 1 6
EMAC-VCC: C166.2 C167.2 L8.1 R103.2 R104.1 R105.1 R106.1 R107.1 R108.1 R109.1 R110.1 R120.2 R127.1 U18.9(GREEN_LED+) U19.14(DVDD33_1) U19.48(DVDD33_2) U20.8(VCC)
EMDC: U19.25(MDC) ; also on sheet 1 6
EMDIO: R105.2 U19.26(MDIO) ; also on sheet 1 6
ENTER: K9.1 R155.2 R156.1
ERXCK: U19.16(RXC) ; also on sheet 1 6
ERXD0: U19.21(RXD0) ; also on sheet 1 6
ERXD1: U19.20(RXD1) ; also on sheet 1 6
ERXD2: U19.19(RXD2) ; also on sheet 1 6
ERXD3: U19.18(RXD3) ; also on sheet 1 6
ERXDV: U19.22(RXDV) ; also on sheet 1 6
ERXERR: R115.1 U19.24(RXER/FXEN) ; also on sheet 1 6
ETXCK: U19.7(TXC) ; also on sheet 1 6
ETXD0: U19.6(TXD0) ; also on sheet 1 6
ETXD1: U19.5(TXD1) ; also on sheet 1 6
ETXD2: U19.4(TXD2) ; also on sheet 1 6
ETXD3: U19.3(TXD3) ; also on sheet 1 6
ETXEN: U19.2(TXEN) ; also on sheet 1 6
ETXERR: TP31.1(TP) ; also on sheet 6
HCEC: HCON1.13(CEC) HU3.1(IN1) HU3.10(OUT1) ; also on sheet 6
HHPD: HR5.1 HR6.1 HU3.5(IN4) HU3.6(OUT4) ; also on sheet 6
HPL: C199.2 R191.2 ; also on sheet 1 6
HPR: C197.2 R182.2 ; also on sheet 1 6
HPVCCIN: C83.1 C84.1 C85.1 C86.1 D2.1(A) J6.3 L1.1 Q8.3(E) R22.1 R24.2 R25.1 R29.2 R103.1 R142.2 R143.1 R200.1 U3.1(VIN) U3.3(CE) VCC_R1.1 ; also on sheet 5 6 7 9 10
HSCL: HCON1.15(SCL) HR7.2 HU3.2(IN2) HU3.9(OUT2) ; also on sheet 6
HSDA: HCON1.16(SDA) HR8.2 HU3.4(IN3) HU3.7(OUT3) ; also on sheet 6
HTX0N: HCON1.9(D0N) HR3.2 HU2.2(IN2) HU2.9(OUT2) ; also on sheet 6
HTX0P: HCON1.7(D0P) HR3.1 HU2.1(IN1) HU2.10(OUT1) ; also on sheet 6
HTX1N: HCON1.6(D1N) HR2.1 HU1.5(IN4) HU1.6(OUT4) ; also on sheet 6
HTX1P: HCON1.4(D1P) HR2.2 HU1.4(IN3) HU1.7(OUT3) ; also on sheet 6
HTX2N: HCON1.3(D2N) HR1.2 HU1.2(IN2) HU1.9(OUT2) ; also on sheet 6
HTX2P: HCON1.1(D2P) HR1.1 HU1.1(IN1) HU1.10(OUT1) ; also on sheet 6
HTXCN: HCON1.12(CLKN) HR4.1 HU2.5(IN4) HU2.6(OUT4) ; also on sheet 6
HTXCP: HCON1.10(CLKP) HR4.2 HU2.4(IN3) HU2.7(OUT3) ; also on sheet 6
INTVDD: C103.1 C104.1 L3.2 TP3.1(TP) U4.17(DCDC3) ; also on sheet 5 7
IPSOUT: C95.2 C97.2 C98.1 C99.2 C100.2 C105.1 C108.1 U4.7(VIN2) U4.13(LDO24IN) U4.14(VIN3) U4.21(APS) U4.34(PS1) U4.35(PS2) U4.40(LDO3IN) U4.44(VIN1)
IR-RX: R143.2 U21.1(OUT) ; also on sheet 6
ISOLATE: R117.1 U19.43(ISOLATE)
JTAG-SEL: J7.1 R135.1 ; also on sheet 6
LDO1SET: R23.1 U4.27(LDO1SET)
LDPS: R109.2 U19.41(LDPS)
LED0: R157.2 U4.18(GPIO1)
LED0/PHYAD0: R112.2 R120.1 U19.9(LED0/PHYAD0)
LED1/PHYAD1: R125.1 U19.10(LED1/PHYAD1)
LED2/PHYAD2: R126.1 U19.12(LED2/PHYAD2)
LED3/PHYAD3: R129.1 U19.13(LED3/PHYAD3)
LED4/PHYAD4: R130.1 U18.12(YELLOW_LED+) U19.15(LED4/PHYAD4)
LRADC0: R148.2 R149.1 ; also on sheet 6 7
MII: R110.2 U19.44(MII/SNIB/RTT3)
MUTE: R200.2 R202.1 ; also on sheet 6
NEXT: K3.1 R149.2 R150.1
NMI#: R30.2 U4.48(IRQ) ; also on sheet 1 6
O-BIAS: C195.2 R181.1 R184.1 U26.3(+IN) U26.5(+IN)
OP_PWR_5V: C194.2 FB7.2 R181.2 R198.1 U26.8(VCC)
PREV: K4.1 R150.2 R151.1
PWFBIN: C170.2 L7.2 U19.8(PWFBIN)
PWFBOUT: C168.2 C169.2 L7.1 R111.1 R113.1 R138.2 R139.1 U19.32(PWFBOUT)
RD+: R83.2 U18.3(RD+) U19.31(TPRX+) U37.1(TD+)
RD-: R93.2 U18.6(RD-) U19.30(TPRX-) U37.3(TD-)
REF: R806.1 R807.1 R808.1 R809.1
RESET#: K1.1 R24.1 U4.25(PWROK) ; also on sheet 1 6 7
RESETB: C172.2 R127.2 U19.42(RESETB)
RPTR: R118.1 U19.40(RPTR)
RTCVDD: C93.2 U4.28(LDO1) ; also on sheet 6 7
RTSET: R116.1 U19.28(RTSET)
RX+: U37.16(TX+) U38.3(RX+)
RX-: U37.14(TX-) U38.6(RX-)
SPDIF-DO: J10.1(GND) ; also on sheet 6
SPEED: R107.2 U19.39(SPEED)
TD+: R128.1 U18.1(TD+) U19.34(TPTX+) U37.6(RD+)
TD-: R134.1 U18.2(TD-) U19.33(TPTX-) U37.8(RD-)
TV-OUT3: C206.1 C207.2 L11.1 R218.1 ; also on sheet 6
TWI0-SCK: R25.2 U4.2(SCK) ; also on sheet 1 6
TWI0-SDA: R22.2 U4.1(SDA) ; also on sheet 1 6
TWI1-SCK: U20.6(SCL) ; also on sheet 1 6 7
TWI1-SDA: U20.5(SDA) ; also on sheet 1 6 7
TX+: U37.11(RX+) U38.1(TX+)
TX-: U37.9(RX-) U38.2(TX-)
UART0-RX: R137.1 ; also on sheet 6
UART0-TX: R136.1 ; also on sheet 6
UBOOT: R156.2 ; also on sheet 6
UP: K7.1 R153.2 R154.1
VOL+: K5.1 R151.2 R152.1
VOL-: K6.1 R152.2 R153.1
N16771581: J1.1(CENTER1) SW1.2(COMMON)
N16771859: OC4.2 U2.8(SS)
N16771865: R17.1 R19.1 U2.7(EN)
N16771869: OC1.1 OL1.1 U2.3(SW)
N16771893: OC1.2 U2.1(BST)
N16771897: R18.2 R21.1 U2.5(FB)
N16809184: R112.1 U18.10(GREEN_LED-)
N16809188: R114.1 U18.11(YELLOW_LED-)
N16809831: C164.2 U19.46(X1) X3.2
N16809845: C165.2 U19.47(X2) X3.1
N16809917: C162.1 R111.2 U18.5(RDCT)
N16809930: C163.2 R113.2 U18.4(TDCT)
N17835602: C90.2 DRAM_R2.2 DRAM_R3.1 OU1.6(FB2)
N17835610: L1.2 OU1.2(LX1)
N17835612: L2.2 OU1.4(LX2)
N17835644: C83.2 OU1.8(FB1) VCC_R1.2 VCC_R2.1
N17835665: DRAM_R1.1 OU1.5(EN2) OU1.7(EN1)
N17911448: HCON1.19(HOT_PLUG_DET) HR5.2
N18050006: C176.2 R142.1 U21.3(VSS)
N18121255: J6.5 R136.2
N18121258: J6.4 R137.2
N19406608: CT1.2 R183.1
N19406610: CT2.2 R192.1
N19406612: CT2.1 R191.1 R193.1 R197.2 U26.7(OUT)
N19406618: CT1.1 R182.1 R185.1 R190.2 U26.1(OUT)
N19406636: R196.2 R197.1 U26.6(-IN)
N19406642: C197.1 R189.1
N19406669: C199.1 R196.1
N19406679: R189.2 R190.1 U26.2(-IN)
N19406868: C196.2 R185.2
N19406887: C198.2 R193.2
N19457857: Q9.1(B) R199.2
N19468421: Q8.1(B) R202.2
N19470821: Q8.2(C) R199.1 R201.1
N21990526: R20.1 U2.6(COMP)
N21990527: OC5.2 R20.2
N21990680: D1.1(ANODE) R29.1
N21992458: D5.1(ANODE) R157.1
N21992873: Q6.1(B) R188.2
N21992874: Q7.1(B) R195.2
N22051068: R808.2 U38.4(REF) U38.5(REF)
N22051158: R809.2 U38.7(REF) U38.8(REF)
N22051174: R807.2 U37.13(CT)
N22051178: R806.2 U37.12(CT)
N22051196: C150.1 R138.1 U37.4(CT)
N22051198: C145.1 R139.2 U37.5(CT)
N22051271: C149.1 R128.2 R134.2
N22051361: C147.2 R83.1 R93.1
N31589069: C102.1 U4.19(GPIO0/LDO)
N31589086: C94.1 U4.26(VINT)
N31589141: L3.1 U4.15(LX3)
N31589329: D2.2(K) R30.1
N31589444: R26.1 U4.37(TS)
N31589623: K2.2 U4.47(PWRON)
N31589693: R28.1 U4.23(BIAS)
N31589718: C96.1 U4.24(VREF)
N31589775: C96.2 C99.1 R27.1 R28.2 U4.22(AGND)
N31590251: L4.1 U4.8(LX2)

Not connected (* = marked no-connect by the designer): HCON1 14(NC)*; J21 1(Y) 3(Pb) 5(Pr); SW1 3(NO); U3 4(FB); U4 3(GPIO3)* 5(GPIO2)* 20(EXTEN)* 29(DC3SET)* 30(BACKUP)* 36(CHGLED/GPO)* 38(BAT1)* 39(BAT2)* 42(BATSENSE)* 43(CHSENSE)* 45(LX1)*; U18 7(NC); U19 27(NC)*; U37 2(NC)* 7(NC)* 10(NC)* 15(NC)*

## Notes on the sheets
sheet 12
- HDMI
sheet 13
- EMAC
- 使用R154来确保8201CP工作在正常模式
- 使用R153来实现Fiber Mode到UTP Mode的转换
- 使用R136来实现CP LED Mode到
  BL LED Mode的转换
- 10M/100M
  Transfomer
- 10M/100M
  RJ45
  Connector
- UART0 口，用于调试软件
- JTAG-SEL下拉到地，JTAG映射到PB口。
- C136, C137和L1尽量靠近PWFBOUT
  C138尽量靠近PWFBIN
- 本接口用于软件调试
  方案设计时，如果不使用SPI NOR flash，
  可以有两个UART可用
- EEPROM存储MAC地址
sheet 14
- IR MODULE
- KEY
- USER LED
- VOL+ 0.19V
- VOL- 0.39V
- MENU 0.6V
- SEARCH 0.80V
- HOME 0.98V
- ESC 1.18V
- ENTER 1.4V
- MUTE
- Android 系统常用按键命名法，按键值以元件value为准
- USER LED指示灯，用PMU的GPIO驱动
sheet 16
- SPDIF OUT
- 光纤
sheet 17
- Head Phone & Speaker
- Gain=R69/R89
- 接电视
- Gain=R87/R88
- 接电视
- Option 4:对音量有特殊需求的客户可对音频输出幅度做进一步放大。
- 该运放的选择关系到最终输出的驱动能力以及音质，所以在成本允许范围内应选择低压供电，
- 且具有rail-to-rail和低噪声的运放。
- 如果选择运放输出，R91/C96，R92/C97组成的补偿网络可以去掉，因为运放内部已经做了补偿。
- R67/R86在选择运放输出时NC，耳机输出时接0R。
- CT18/CT19在耳机输出时建议用220uF以提升低频分量。
sheet 21
- POWER/PMU
- 靠近LDO3IN放置
- 靠近VIN1放置
- 系统上电指示
- 电源分配表：
- AXP209说明：
- DCDC2  0.7-2.27V 可调/1.6A Max---默认电压可设置
  DCDC3  0.7-3.5V 可调/1.2A Max--默认电压可设置
  LDO2   1.8-3.3V可调/200mA--默认电压可设置
  LDO3   0.7-3.5V可调/400mA Max---默认电压可设置
  LDO4   1.8V-3.3V可调/200mA Max--默认电压可设置
  GPIO-LDO 1.8-3.5V可调 50mA Max --需开机设置输出电压
  DC3SET ---DCDC3输出电压设置PIN
  LDO1SET ---LDO1输出电压设置PIN
  PWM Charger  1.8A Max
  DC3SET\LDO1SET 高电平接VINT
- 电源名称
- 输出电压
- 最大供电能力
- 预计用途
- AXP209 DCDC2
- 1.25V
- 1600mA
- CPU
- AXP209 DCDC3
- 1.2V
- 1200mA
- INTERLOGIC/DLL/USB
- AXP209 LDO1
- 1.3V
- 30mA
- RTC
- AXP209 LDO2
- 3V
- 200mA
- (ENABLE:5V/3V3/2V5)
- AVCC
- AXP209 LDO3
- 2.8V
- 200mA
- CSI0-IO
- AXP209 LDO4
- 2.8V
- 200mA
- CSI1-IO
- SY8021L DCDC1
- 3.3V
- 1000mA
- NAND/HPVCC/USB/HDMI/TVIN/TVOUT/PIO/PLL/
- SY8021L DCDC2
- 1.5V
- 1000mA
- EMAC/IR/LCD/NOR/RS232/IT6400FB
- DDR3
- DC3SET
- DCDC3 Voltage
- LDO1SET
- LDO1 Voltage
- IT6400FB
- 2.5V
- 200mA
- TVIN
- HIGH
- 3.3V
- HIGH
- 3.3V
- RT9266PE
- 5V
- 1000mA
- HDMI/USB/LCD/PS2
- LOW
- 1.8V
- MP1482DS
- 5V
- 2000mA
- PMU
- Floating
- 1.2V
- LOW
- 1.3V
sheet 22
- 12V TO 5V FOR PMU
- ACIN
- 5.25v
- Vout = 0.923 x (1 + R1/R2)
  R2 < 100K
- 3V3-1V5
- 2V5
- 有改动，与PAD方案不同
- Vout = 0.6*(1+DRAM_R1/DRAM_R2)
